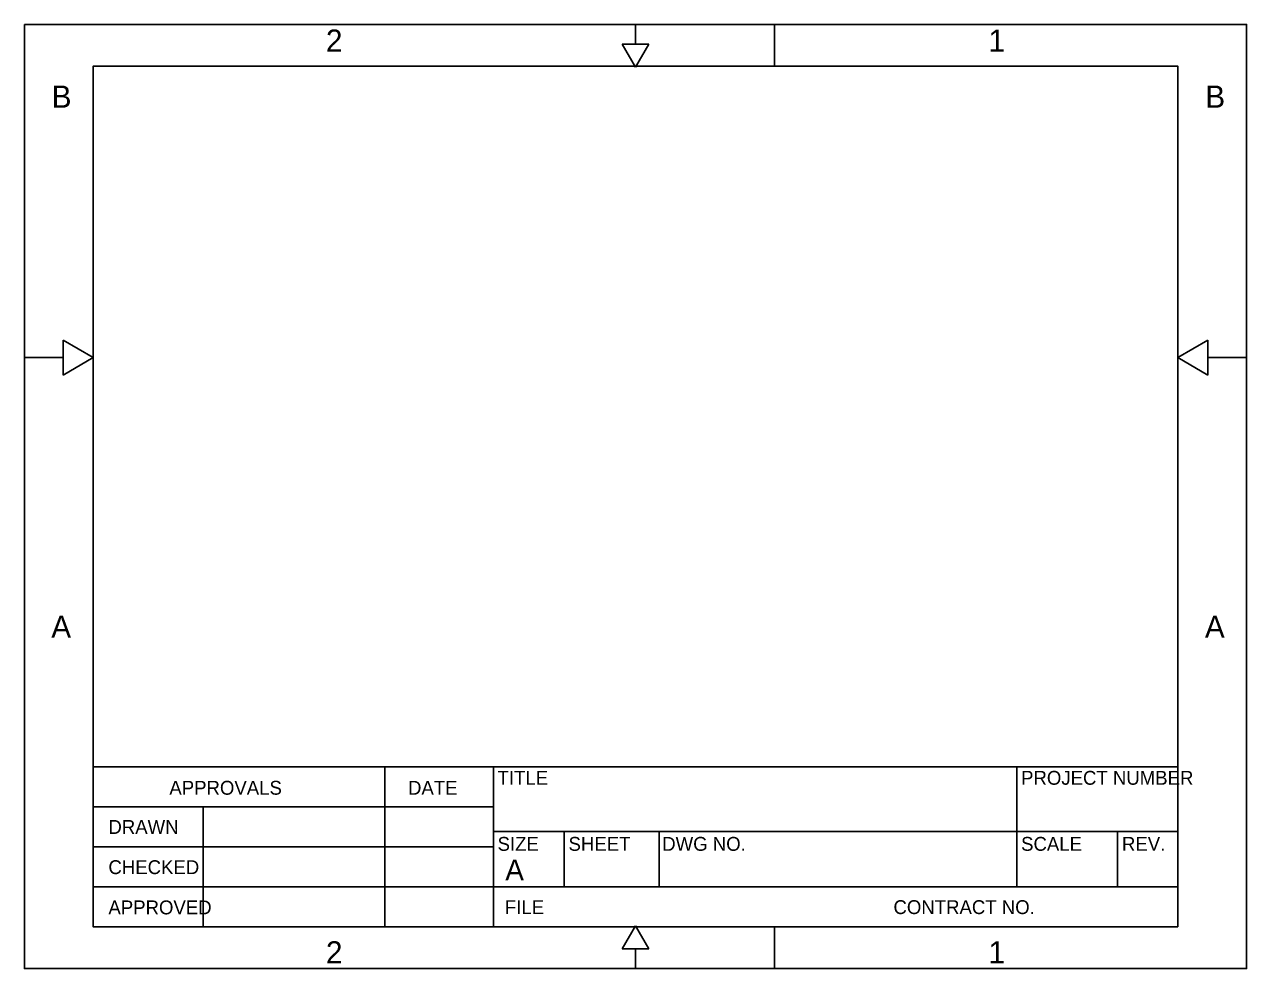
# Model space of a CAD drawing. Extents: x 0 to 0.917, y 0 to 0.708.
import ezdxf

# ---------------------------------------------------------------- set-up
doc = ezdxf.new("R2010")
doc.units = 0
for name, color, linetype in [('Border_outline', 7, 'Continuous'), ('BorderPlot', 7, 'Continuous'), ('TitleBlock', 7, 'Continuous'), ('TitleBlockText', 7, 'Continuous')]:
    doc.layers.add(name, color=color, linetype=linetype)

msp = doc.modelspace()

# ---------------------------------------------------------------- linework, layer by layer
at = {"layer": 'Border_outline'}
for p, q in [((0.45833, 0.69363), (0.45833, 0.70833)), ((0.5625, 0.70833), (0.5625, 0.67708)), ((0.45833, 0.6762), (0.44827, 0.69363)), ((0.44827, 0.69363), (0.4684, 0.69363)), ((0.45833, 0.6762), (0.4684, 0.69363)), ((0.05167, 0.45833), (0.02907, 0.47138)), ((0.02907, 0.47138), (0.02907, 0.44528)), ((0.865, 0.45833), (0.8876, 0.47138)), ((0.8876, 0.47138), (0.8876, 0.44528)), ((0.02907, 0.45833), (0, 0.45833)), ((0.02907, 0.44528), (0.05167, 0.45833)), ((0.8876, 0.44528), (0.865, 0.45833)), ((0.8876, 0.45833), (0.91667, 0.45833)), ((0.45833, 0.03213), (0.44827, 0.0147)), ((0.45833, 0.03213), (0.4684, 0.0147)), ((0.5625, 0), (0.5625, 0.03125)), ((0.44827, 0.0147), (0.4684, 0.0147)), ((0.45833, 0.0147), (0.45833, 0))]:
    msp.add_line(p, q, dxfattribs=at)
msp.add_lwpolyline([(0.865, 0.03125), (0.05167, 0.03125), (0.05167, 0.67708), (0.865, 0.67708)], close=True, dxfattribs=at)
at = {"layer": 'BorderPlot'}
msp.add_lwpolyline([(0, 0.70833), (0.91667, 0.70833), (0.91667, 0), (0, 0)], close=True, dxfattribs=at)
msp.add_lwpolyline([(0, 0.70833), (0.91667, 0.70833), (0.91667, 0), (0, 0)], close=True, dxfattribs=at)
at = {"layer": 'TitleBlock'}
for p, q in [((0.05167, 0.15125), (0.865, 0.15125)), ((0.27038, 0.03125), (0.27038, 0.15125)), ((0.3517, 0.03125), (0.3517, 0.15125)), ((0.74431, 0.06125), (0.74431, 0.15125)), ((0.05167, 0.12125), (0.3517, 0.12125)), ((0.13396, 0.03125), (0.13396, 0.12125)), ((0.3517, 0.10292), (0.865, 0.10292)), ((0.40489, 0.06125), (0.40489, 0.10292)), ((0.47606, 0.06125), (0.47606, 0.10292)), ((0.81988, 0.06125), (0.81988, 0.10292)), ((0.05167, 0.09125), (0.3517, 0.09125)), ((0.05167, 0.06125), (0.865, 0.06125)), ((0.865, 0.03125), (0.865, 0.03125))]:
    msp.add_line(p, q, dxfattribs=at)

# ---------------------------------------------------------------- texts
at = {"layer": 'Border_outline'}
for s, p in [('2', (0.22613, 0.68784)), ('2', (0.22613, 0.68784)), ('1', (0.72308, 0.68784)), ('B', (0.02043, 0.64582)), ('B', (0.88573, 0.64582)), ('A', (0.02013, 0.24816)), ('A', (0.88543, 0.24816)), ('2', (0.22613, 0.00383)), ('1', (0.72308, 0.00383))]:
    msp.add_text(s, height=0.01667, dxfattribs=at).set_placement(p)
at = {"layer": 'TitleBlock'}
msp.add_text('A', height=0.01562, dxfattribs=at).set_placement((0.3607, 0.06619))
at = {"layer": 'TitleBlockText'}
for s, height, p in [('TITLE', 0.010417, (0.35488, 0.13789)), ('PROJECT NUMBER', 0.0104167, (0.74755, 0.13789)), ('APPROVALS', 0.010417, (0.1087, 0.13042)), ('DATE', 0.010417, (0.28772, 0.13042)), ('DRAWN', 0.010417, (0.06299, 0.10104)), ('SIZE', 0.010417, (0.35488, 0.08834)), ('SHEET', 0.010417, (0.4081, 0.08834)), ('DWG NO.', 0.010417, (0.47839, 0.08834)), ('SCALE', 0.010417, (0.74755, 0.08834)), ('REV.', 0.010417, (0.82321, 0.08834)), ('CHECKED', 0.010417, (0.06299, 0.07086)), ('APPROVED', 0.010417, (0.06299, 0.04067)), ('FILE', 0.010417, (0.36032, 0.04088)), ('CONTRACT NO.', 0.0104167, (0.65183, 0.04088))]:
    msp.add_text(s, height=height, dxfattribs=at).set_placement(p)

doc.saveas('drawing.dxf')
